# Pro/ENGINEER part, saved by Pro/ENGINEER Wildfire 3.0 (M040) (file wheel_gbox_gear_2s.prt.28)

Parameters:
  PTNUM = "A_1C_1MYW25050A"
  PTNAME = "HUBLESS_SPUR_GEAR_MODULE_2.5"
  MFG = "Stock_Drive_Products"
  WEIGHT = "*"
  MATERIAL = "STEEL"

Other parameters: TEETH, MODULE, OUTSIDE_DIA, D73, D76, D77, D67, D78

Family table entries: GEOMETRY, 3GEOMETRY, MP_DENSITY, ~"x, PRO_MP_ALT_MASS, ~"x, value(NO_val), PRO_MP_ALT_VOLUME, ~"x, PRO_MP_ALT_AREA, ~"x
